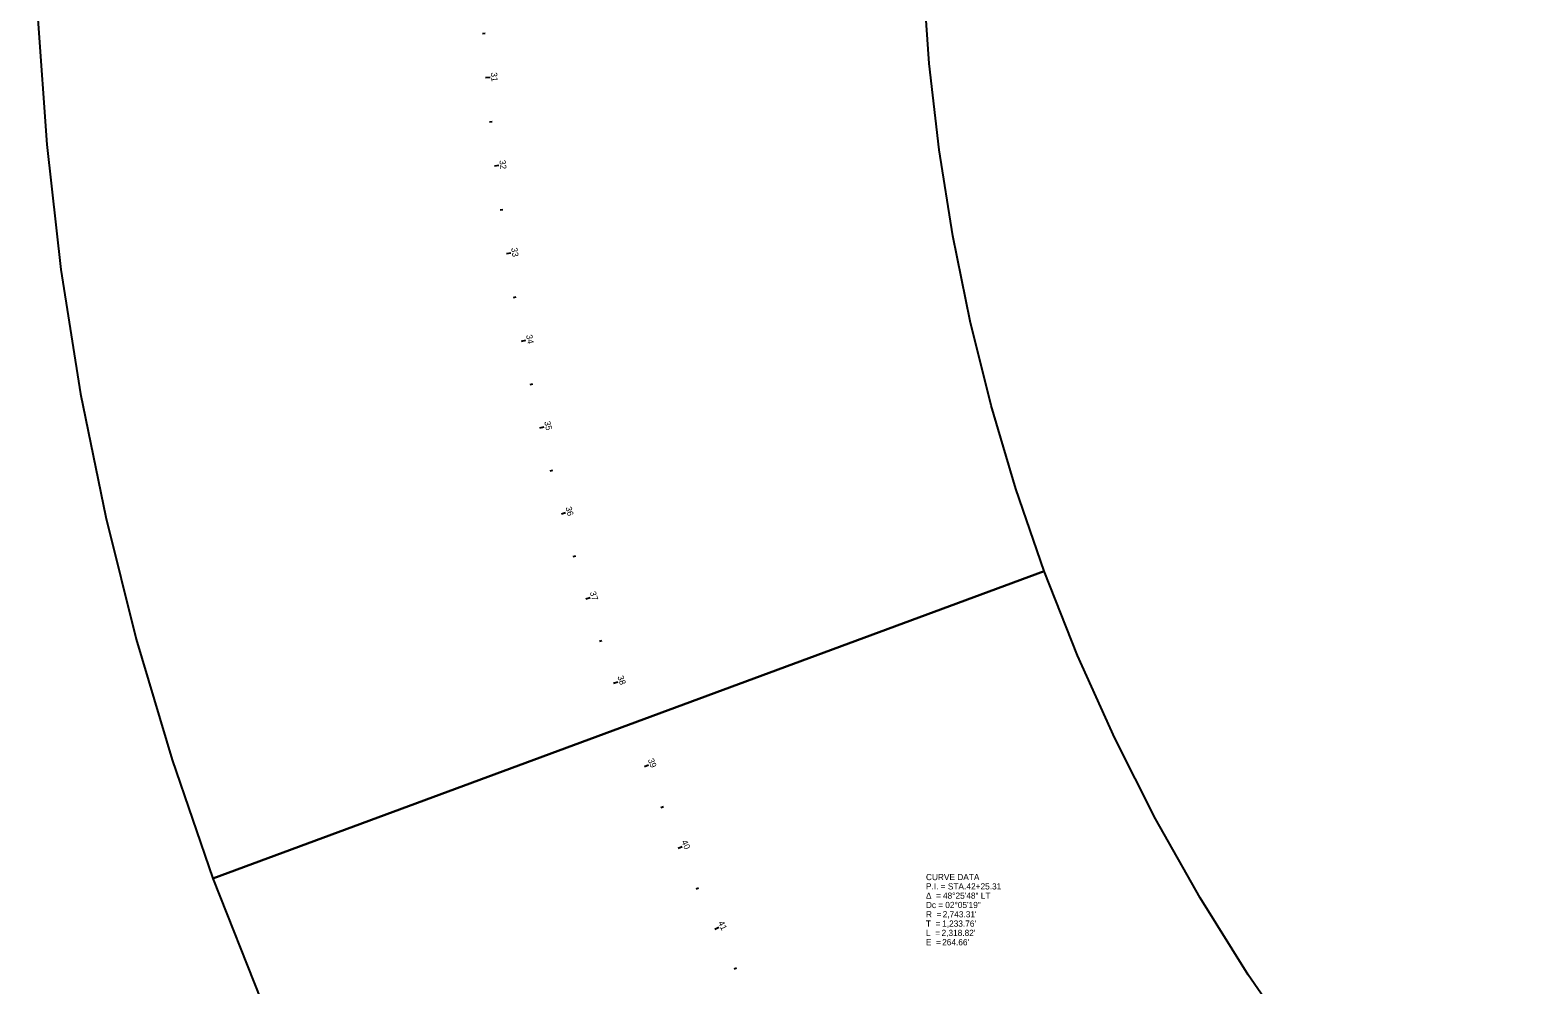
# Model space of a CAD drawing. Extents: x 75725 to 90554, y 518585 to 527848.
# Drawn here: x 87224 to 88925, y 519689 to 520766 of the extents above; entities that cross this region are included whole.
import ezdxf

# ---------------------------------------------------------------- set-up
doc = ezdxf.new("R2010")
doc.units = 0
for name, color, linetype in [('GE_P_Alignment_100_Curve_Data', 7, 'Continuous'), ('GE_P_Alignment_100_Stations', 7, 'Continuous'), ('SH_Named_Boundary', 7, 'Continuous')]:
    doc.layers.add(name, color=color, linetype=linetype)

msp = doc.modelspace()

# ---------------------------------------------------------------- linework, layer by layer
at = {"layer": 'GE_P_Alignment_100_Stations'}
for p, q in [((87734.2, 520762.4), (87737.2, 520762.6)), ((87737.7, 520712.5), (87742.7, 520712.9)), ((87742.2, 520662.7), (87745.2, 520663)), ((87747.6, 520613), (87752.6, 520613.6)), ((87753.9, 520563.4), (87756.9, 520563.8)), ((87761.1, 520514), (87766.1, 520514.7)), ((87769.2, 520464.6), (87772.2, 520465.1)), ((87778.2, 520415.4), (87783.1, 520416.4)), ((87788.1, 520366.4), (87791, 520367)), ((87798.9, 520317.6), (87803.8, 520318.7)), ((87810.6, 520269), (87813.5, 520269.7)), ((87823.1, 520220.6), (87827.9, 520221.9)), ((87836.6, 520172.4), (87839.4, 520173.3)), ((87850.9, 520124.5), (87855.6, 520126)), ((87866, 520076.9), (87868.9, 520077.8)), ((87882.1, 520029.5), (87886.8, 520031.2)), ((87899, 519982.5), (87901.8, 519983.5)), ((87916.8, 519935.7), (87921.4, 519937.6)), ((87935.4, 519889.3), (87938.2, 519890.5)), ((87954.8, 519843.3), (87959.4, 519845.3)), ((87975.1, 519797.6), (87977.9, 519798.8)), ((87996.2, 519752.3), (88000.8, 519754.4)), ((88018.2, 519707.3), (88020.9, 519708.7))]:
    msp.add_line(p, q, dxfattribs=at)
at = {"layer": 'SH_Named_Boundary'}
for points in [[(88223.6, 521168.6), (87223.7, 521155.8), (87225.3, 521035.8), (87227.4, 520909.7), (87232.5, 520778.4), (87242.4, 520636.9), (87258.5, 520496), (87280.7, 520355.8), (87309, 520216.8), (87343.4, 520079.2), (87383.8, 519943.2), (87430, 519809.1), (88368, 520155.8), (88336, 520248.6), (88308.1, 520342.7), (88284.3, 520437.9), (88264.7, 520534), (88249.3, 520630.9), (88238.2, 520728.4), (88231.4, 520826.3), (88227.1, 520934.8), (88225.2, 521048.7)], [(88368, 520155.8), (87430, 519809.1), (87484.4, 519671.7), (87545, 519536.9), (87611.6, 519405), (87684.2, 519276.3), (87762.6, 519151.1), (87846.6, 519029.5), (87936.1, 518911.9), (88030.8, 518798.5), (88130.6, 518689.5), (88235.3, 518585.2), (88924.9, 519309.3), (88852.6, 519381.4), (88783.5, 519456.8), (88718, 519535.3), (88656.1, 519616.6), (88598, 519700.7), (88543.8, 519787.3), (88493.6, 519876.4), (88447.5, 519967.6), (88405.6, 520060.8)]]:
    msp.add_lwpolyline(points, close=True, dxfattribs=at)

# ---------------------------------------------------------------- texts
at = {"layer": 'GE_P_Alignment_100_Curve_Data'}
for s, p in [('CURVE DATA', (88234.5, 519807.4)), ('Δ  = ', (88234.5, 519786.4)), ('P.I. = STA. ', (88234.5, 519796.9)), ('48°25\'48" LT', (88253.7, 519786.4)), ('42+25.31', (88280.2, 519796.9)), ('Dc = ', (88234.5, 519775.9)), ('02°05\'19"', (88256.3, 519775.9)), ('T  = ', (88234.5, 519754.9)), ('R  = ', (88234.5, 519765.4)), ("1,233.76'", (88252.8, 519754.9)), ("2,743.31'", (88253.4, 519765.4)), ('L  = ', (88234.5, 519744.4)), ("2,318.82'", (88252.1, 519744.4)), ('E  = ', (88234.5, 519733.9)), ("264.66'", (88252.8, 519733.9))]:
    msp.add_text(s, height=7, dxfattribs=at).set_placement(p)
at = {"layer": 'GE_P_Alignment_100_Stations'}
for s, rotation, p in [('31', 274.6237, (87743.6, 520718.1)), ('32', 276.7123, (87753.2, 520619.1)), ('33', 278.8009, (87766.5, 520520.2)), ('34', 280.8894, (87783.3, 520421.9)), ('35', 282.978, (87803.7, 520324.3)), ('36', 285.0666, (87827.7, 520227.6)), ('37', 287.1551, (87855.1, 520131.9)), ('38', 289.2437, (87886.2, 520036.8)), ('39', 291.3323, (87920.6, 519943.1)), ('40', 293.4208, (87958.4, 519850.9)), ('41', 295.5094, (87999.7, 519759.5))]:
    msp.add_text(s, height=7, rotation=rotation, dxfattribs=at).set_placement(p)

doc.saveas('drawing.dxf')
